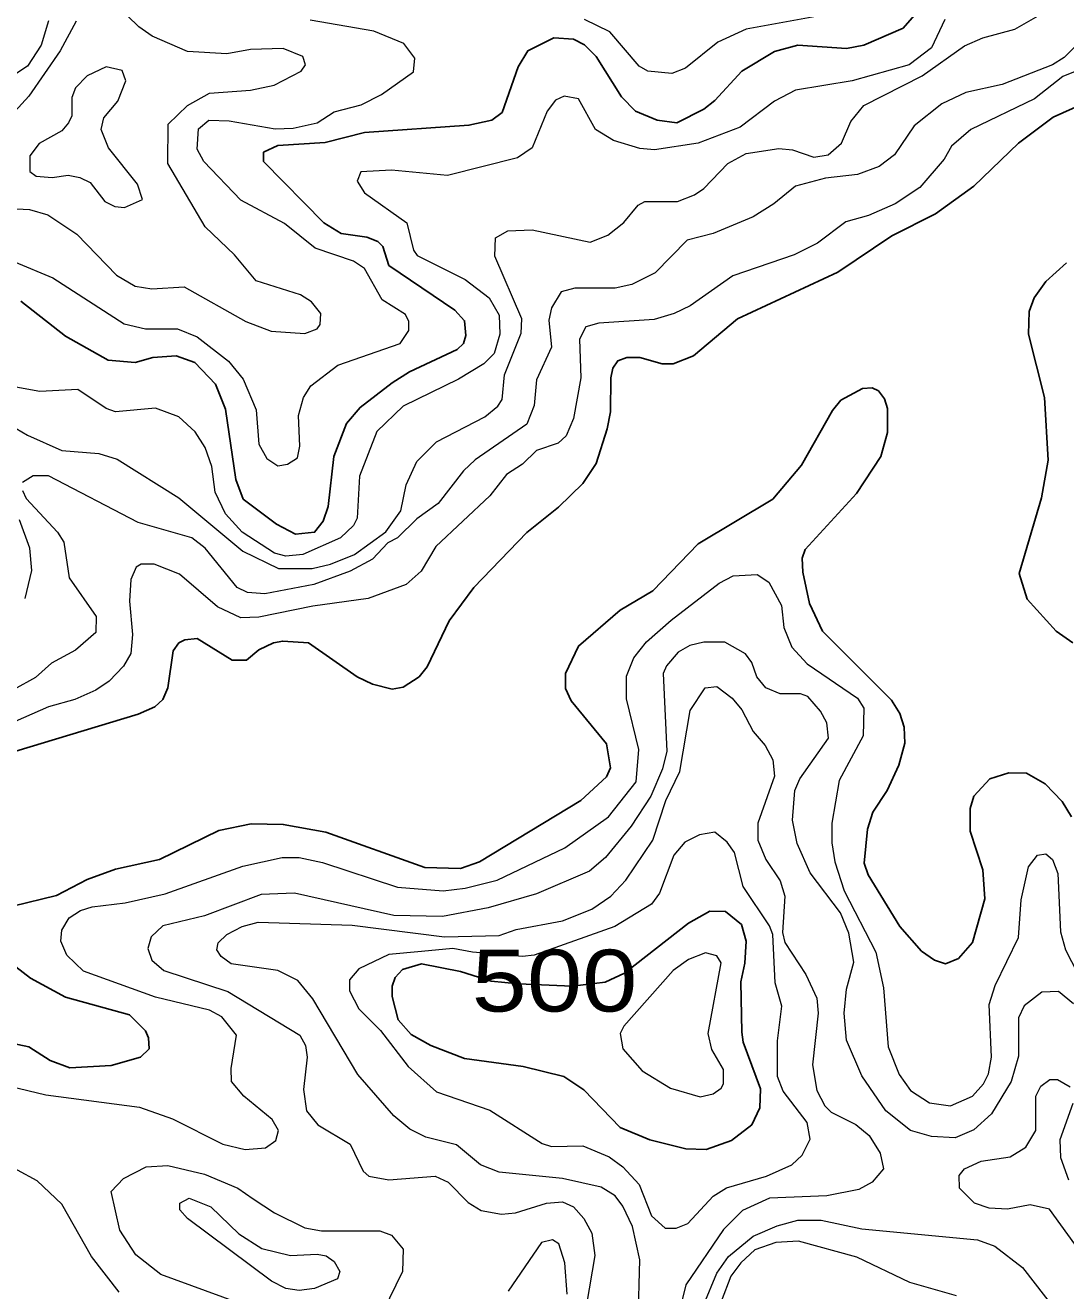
# Model space of a CAD drawing. Extents: x 577 to 602.9, y 7483.8 to 7511.6.
# Drawn here: x 599.479 to 600.825, y 7491.079 to 7492.716 of the extents above; entities that cross this region are included whole.
import ezdxf
from ezdxf.enums import TextEntityAlignment as Align

# ---------------------------------------------------------------- set-up
doc = ezdxf.new("R2010")
doc.units = 0
doc.header["$LTSCALE"] = 0.032
doc.layers.add('1', color=7, linetype='Continuous', lineweight=25)
doc.layers.add('2', color=7, linetype='Continuous', lineweight=13)
doc.layers.add('61', color=7, linetype='Continuous')

msp = doc.modelspace()

# ---------------------------------------------------------------- linework, layer by layer
at = {"layer": '1'}
for points in [[(600.6496, 7492.7525), (600.6146, 7492.712), (600.5637, 7492.6897), (600.5414, 7492.6857), (600.4786, 7492.6897), (600.4484, 7492.6818), (600.4063, 7492.6563), (600.3713, 7492.6182), (600.357, 7492.607), (600.322, 7492.5895), (600.2965, 7492.5927), (600.2687, 7492.6046), (600.2504, 7492.6229), (600.2178, 7492.6754), (600.2027, 7492.6905), (600.1884, 7492.6977), (600.1629, 7492.6993), (600.1295, 7492.6826), (600.1168, 7492.6619), (600.0961, 7492.603), (600.0826, 7492.5927), (600.0532, 7492.5863), (599.918, 7492.5768), (599.8671, 7492.5641), (599.8059, 7492.5601), (599.7876, 7492.5514), (599.7876, 7492.5394), (599.8655, 7492.4599), (599.8878, 7492.4464), (599.9212, 7492.4416), (599.9355, 7492.4361), (599.9419, 7492.4297), (599.9498, 7492.405), (600.0349, 7492.347), (600.0476, 7492.3335), (600.0492, 7492.3144), (600.046, 7492.3041), (600.0381, 7492.2961), (599.9761, 7492.2675), (599.9538, 7492.2532), (599.9125, 7492.2214), (599.895, 7492.2007), (599.8783, 7492.1577), (599.8711, 7492.0933), (599.8647, 7492.0743), (599.8536, 7492.0599), (599.829, 7492.0576), (599.8043, 7492.0703), (599.7614, 7492.1029), (599.7518, 7492.1283), (599.7383, 7492.219), (599.7256, 7492.2516), (599.6986, 7492.2794), (599.6747, 7492.2882), (599.6445, 7492.2858), (599.6214, 7492.2794), (599.5864, 7492.2826), (599.5316, 7492.3136), (599.4735, 7492.3589)], [(600.904, 7492.6396), (600.8086, 7492.5967), (600.7641, 7492.5633), (600.706, 7492.5076), (600.6567, 7492.4718), (600.6003, 7492.4432), (600.5303, 7492.3963), (600.4007, 7492.3359), (600.3434, 7492.2882), (600.3172, 7492.2778), (600.3029, 7492.2778), (600.2743, 7492.2858), (600.2576, 7492.2858), (600.2456, 7492.2818), (600.2393, 7492.2723), (600.2369, 7492.2595), (600.2361, 7492.2158), (600.2321, 7492.1935), (600.2178, 7492.149), (600.2003, 7492.1228), (600.1688, 7492.0923), (600.1279, 7492.0598), (600.0596, 7491.9884), (600.0278, 7491.9454), (599.9991, 7491.8858), (599.9888, 7491.8731), (599.9681, 7491.8596), (599.9538, 7491.8572), (599.9284, 7491.8635), (599.9085, 7491.8731), (599.8457, 7491.9168), (599.8123, 7491.9192), (599.8003, 7491.9168), (599.7813, 7491.9081), (599.7653, 7491.8945), (599.7471, 7491.8945), (599.7017, 7491.9224), (599.6858, 7491.9208), (599.6779, 7491.9168), (599.6707, 7491.9065), (599.6636, 7491.8588), (599.6572, 7491.8437), (599.6469, 7491.8341), (599.6254, 7491.8246), (599.4672, 7491.7769)], [(600.8341, 7491.9168), (600.8126, 7491.9319), (600.7752, 7491.9733), (600.7649, 7492.0067), (600.7935, 7492.1045), (600.8023, 7492.153), (600.7975, 7492.2341), (600.7768, 7492.316), (600.7776, 7492.3454), (600.784, 7492.3629), (600.7991, 7492.3844), (600.8261, 7492.4082)], [(599.4632, 7491.5765), (599.5196, 7491.59), (599.5594, 7491.6107), (599.596, 7491.6242), (599.6532, 7491.6369), (599.7296, 7491.6743), (599.7717, 7491.683), (599.8131, 7491.6822), (599.8679, 7491.6719), (599.996, 7491.6266), (600.0421, 7491.625), (600.0667, 7491.6337), (600.1979, 7491.7132), (600.2313, 7491.7435), (600.2361, 7491.7554), (600.2313, 7491.7864), (600.1852, 7491.8421), (600.178, 7491.858), (600.178, 7491.8771), (600.1947, 7491.9128), (600.2488, 7491.959), (600.291, 7491.9844), (600.3498, 7492.0448), (600.446, 7492.1029), (600.4834, 7492.1466), (600.5232, 7492.2174), (600.5343, 7492.2309), (600.5621, 7492.246), (600.5748, 7492.2468), (600.5828, 7492.2428), (600.5907, 7492.2325), (600.5947, 7492.2198), (600.5947, 7492.1888), (600.586, 7492.1577), (600.5542, 7492.11), (600.4882, 7492.0377), (600.4842, 7492.0265), (600.485, 7492.0083), (600.4937, 7491.9677), (600.5104, 7491.9319), (600.5995, 7491.8429), (600.6106, 7491.8254), (600.6162, 7491.8079), (600.617, 7491.7872), (600.609, 7491.7586), (600.5939, 7491.726), (600.5756, 7491.6981), (600.5685, 7491.6759), (600.5645, 7491.6321), (600.5693, 7491.617), (600.6106, 7491.5502), (600.6385, 7491.5184), (600.6552, 7491.5065), (600.6695, 7491.5017), (600.6862, 7491.5089), (600.7045, 7491.5296), (600.7204, 7491.586), (600.718, 7491.6234), (600.7013, 7491.6735), (600.7013, 7491.7029), (600.706, 7491.7188), (600.7267, 7491.7411), (600.7514, 7491.749)], [(600.7514, 7491.749), (600.7744, 7491.7482), (600.7983, 7491.7347), (600.8205, 7491.7117), (600.8325, 7491.6918)], [(599.4282, 7491.4063), (599.4839, 7491.3944), (599.5117, 7491.3769), (599.5371, 7491.3673), (599.5904, 7491.3705), (599.6286, 7491.3809), (599.6397, 7491.392), (599.6389, 7491.4063), (599.6349, 7491.4151), (599.6143, 7491.4357), (599.5316, 7491.4588), (599.4862, 7491.4834), (599.452, 7491.5097)]]:
    msp.add_lwpolyline(points, dxfattribs=at)
msp.add_lwpolyline([(600.0422, 7491.4917), (600.082, 7491.4793), (600.1172, 7491.4761), (600.1869, 7491.4728), (600.2293, 7491.478), (600.2544, 7491.4898), (600.3371, 7491.5542), (600.3649, 7491.5701), (600.3848, 7491.5693), (600.4055, 7491.5526), (600.4118, 7491.5311), (600.4102, 7491.5025), (600.4047, 7491.4787), (600.4063, 7491.4135), (600.4079, 7491.4007), (600.4301, 7491.3403), (600.4293, 7491.3157), (600.419, 7491.2934), (600.3927, 7491.2735), (600.3601, 7491.2616), (600.3339, 7491.2624), (600.287, 7491.2743), (600.2488, 7491.2902), (600.2019, 7491.3387), (600.1757, 7491.3562), (600.1232, 7491.3689), (600.0476, 7491.3793), (600.0039, 7491.396), (599.9785, 7491.4103), (599.9618, 7491.4294), (599.9538, 7491.4596), (599.9538, 7491.4731), (599.9578, 7491.4842), (599.9673, 7491.4946), (599.992, 7491.5017)], close=True, dxfattribs=at)
at = {"layer": '2'}
for points in [[(599.452, 7492.479), (599.4847, 7492.4774), (599.5085, 7492.4703), (599.5459, 7492.4456), (599.5976, 7492.3923), (599.6214, 7492.378), (599.6429, 7492.3748), (599.685, 7492.3772), (599.7646, 7492.3327), (599.7972, 7492.32), (599.8409, 7492.3168), (599.8568, 7492.3231), (599.8608, 7492.3287), (599.8616, 7492.343), (599.8496, 7492.3581), (599.8353, 7492.3669), (599.7781, 7492.3852), (599.7502, 7492.4186), (599.7121, 7492.4551), (599.6636, 7492.537), (599.6644, 7492.5879), (599.689, 7492.6118), (599.7176, 7492.6277), (599.7709, 7492.6317), (599.8011, 7492.638), (599.8361, 7492.6563), (599.8417, 7492.6643), (599.8385, 7492.6754), (599.8131, 7492.6857), (599.7709, 7492.6842), (599.7399, 7492.6786), (599.689, 7492.6818), (599.6437, 7492.7016), (599.6262, 7492.7136), (599.5968, 7492.7422)], [(599.5093, 7492.7215), (599.4998, 7492.6897), (599.4823, 7492.6627), (599.4322, 7492.6301)], [(599.5451, 7492.7207), (599.5244, 7492.6826), (599.4839, 7492.6237), (599.4338, 7492.5696)], [(599.4656, 7492.4098), (599.5149, 7492.3891), (599.6071, 7492.3295), (599.6349, 7492.3231), (599.6763, 7492.3231), (599.7017, 7492.3128), (599.7423, 7492.281), (599.7614, 7492.2579), (599.7781, 7492.2182), (599.7813, 7492.1737), (599.7916, 7492.1554), (599.8059, 7492.1458), (599.8186, 7492.1482), (599.8313, 7492.1562), (599.8345, 7492.1713), (599.8329, 7492.211), (599.8393, 7492.2341), (599.8488, 7492.2492), (599.8838, 7492.2762), (599.9641, 7492.3041), (599.9753, 7492.3208), (599.9753, 7492.3327), (599.9713, 7492.3414), (599.9411, 7492.3605), (599.918, 7492.4011), (599.9037, 7492.4106), (599.8544, 7492.4273), (599.8147, 7492.4591), (599.7582, 7492.4893), (599.7105, 7492.5394), (599.7017, 7492.5553), (599.7033, 7492.5816), (599.7168, 7492.5927), (599.7431, 7492.5919), (599.8027, 7492.5816), (599.8258, 7492.5824), (599.8568, 7492.5895), (599.8791, 7492.6038), (599.914, 7492.6126), (599.9403, 7492.6261), (599.9816, 7492.6555), (599.9832, 7492.673), (599.9689, 7492.6921), (599.93, 7492.708), (599.848, 7492.7223)], [(600.6687, 7492.7231), (600.6512, 7492.6865), (600.6225, 7492.6643), (600.5486, 7492.6436), (600.4754, 7492.6317), (600.4484, 7492.6174), (600.4039, 7492.584), (600.3498, 7492.5633), (600.2933, 7492.5545), (600.2743, 7492.5561), (600.2401, 7492.5665), (600.217, 7492.5808), (600.1947, 7492.6205), (600.1765, 7492.6237), (600.1653, 7492.6189), (600.1542, 7492.6046), (600.1351, 7492.5569), (600.116, 7492.5442), (600.0254, 7492.5211), (599.953, 7492.5283), (599.9133, 7492.5259), (599.9085, 7492.514), (599.918, 7492.4989), (599.9729, 7492.4599), (599.9816, 7492.4249), (599.9864, 7492.4178), (600.0484, 7492.3868), (600.0794, 7492.3629), (600.0922, 7492.3406), (600.093, 7492.316), (600.0858, 7492.2913), (600.0723, 7492.2778), (600.0397, 7492.2579), (599.9681, 7492.223), (599.9339, 7492.1904), (599.9117, 7492.1323), (599.9085, 7492.0782), (599.9037, 7492.0687), (599.887, 7492.0528), (599.8385, 7492.0313), (599.8162, 7492.0289), (599.8019, 7492.0329), (599.7598, 7492.0599), (599.7383, 7492.0838), (599.7248, 7492.1116), (599.7208, 7492.145), (599.7121, 7492.1697), (599.6993, 7492.1896), (599.6779, 7492.2094), (599.6477, 7492.2206), (599.596, 7492.2158), (599.584, 7492.2198), (599.5475, 7492.2444), (599.4982, 7492.242), (599.4672, 7492.2476)], [(599.5268, 7492.1657), (599.5745, 7492.1617), (599.5984, 7492.1546), (599.6779, 7492.1045), (599.7606, 7492.0353), (599.8067, 7492.013), (599.8504, 7492.013), (599.8743, 7492.0186), (599.9053, 7492.0313), (599.9459, 7492.0607), (599.9649, 7492.0878), (599.9721, 7492.1212), (599.9856, 7492.1514), (600.0111, 7492.1768), (600.0739, 7492.2094), (600.0906, 7492.223), (600.0961, 7492.2317), (600.0993, 7492.2635), (600.1208, 7492.3176), (600.1216, 7492.3359), (600.0866, 7492.417), (600.0874, 7492.4408), (600.1033, 7492.4496), (600.1351, 7492.4512), (600.2099, 7492.4353), (600.2329, 7492.444), (600.2536, 7492.4607), (600.2719, 7492.483), (600.2806, 7492.4877), (600.3228, 7492.4877), (600.345, 7492.4965), (600.357, 7492.5044), (600.388, 7492.537), (600.4118, 7492.5498), (600.454, 7492.5561), (600.4715, 7492.5545), (600.4993, 7492.545), (600.5176, 7492.5482), (600.5351, 7492.5633), (600.547, 7492.5911), (600.5637, 7492.6118), (600.6392, 7492.65), (600.6941, 7492.6889), (600.718, 7492.6993), (600.7593, 7492.7104), (600.7895, 7492.7279)], [(600.5065, 7492.7279), (600.4118, 7492.7104), (600.3752, 7492.6937), (600.3331, 7492.6603), (600.3156, 7492.6531), (600.2846, 7492.6563), (600.2735, 7492.6627), (600.2353, 7492.7072), (600.2027, 7492.7231)], [(600.8444, 7492.6953), (600.8229, 7492.6738), (600.8078, 7492.6643), (600.7426, 7492.6388), (600.6957, 7492.6285), (600.6647, 7492.6142), (600.6289, 7492.5856), (600.6035, 7492.5482), (600.5836, 7492.5331), (600.5558, 7492.5227), (600.5144, 7492.518), (600.4754, 7492.5076), (600.4476, 7492.4846), (600.4206, 7492.4679), (600.3689, 7492.4464)], [(600.8738, 7492.6706), (600.8213, 7492.6492), (600.7848, 7492.6205), (600.7021, 7492.5808), (600.6774, 7492.5593), (600.6679, 7492.5426), (600.6361, 7492.506), (600.6043, 7492.4846), (600.5701, 7492.4695), (600.5406, 7492.4615), (600.5041, 7492.4337), (600.4739, 7492.4186), (600.3943, 7492.3915), (600.3395, 7492.3526), (600.3188, 7492.343), (600.2926, 7492.3351), (600.221, 7492.3303), (600.2043, 7492.3255), (600.1963, 7492.3096), (600.1979, 7492.2595), (600.1884, 7492.207), (600.1788, 7492.1848), (600.1685, 7492.1752), (600.1407, 7492.1657), (600.1224, 7492.1482), (600.1017, 7492.1347), (600.0802, 7492.1069), (600.0103, 7492.0417), (599.9912, 7492.0098), (599.9721, 7491.9924), (599.9228, 7491.9741), (599.8512, 7491.9645), (599.7813, 7491.9502), (599.7582, 7491.9494), (599.728, 7491.9637), (599.6787, 7492.0059), (599.6461, 7492.0186), (599.6294, 7492.0186), (599.623, 7492.0146), (599.6159, 7491.9987)], [(600.3689, 7492.4464), (600.3355, 7492.4376), (600.2941, 7492.3955), (600.2639, 7492.3804), (600.2425, 7492.3756), (600.19, 7492.3756), (600.1725, 7492.3709), (600.1598, 7492.3502), (600.1566, 7492.3343), (600.1598, 7492.2993), (600.1407, 7492.2571), (600.1375, 7492.2237), (600.1279, 7492.1999), (600.0612, 7492.1538), (600.046, 7492.1395), (600.0134, 7492.0973), (599.9856, 7492.0774), (599.961, 7492.0528), (599.9482, 7492.0464), (599.9284, 7492.025), (599.8997, 7492.0098), (599.8528, 7491.9924), (599.7892, 7491.9804), (599.7669, 7491.982), (599.7534, 7491.9884), (599.7121, 7492.0393), (599.6946, 7492.0528), (599.6254, 7492.0727), (599.5093, 7492.1331), (599.4894, 7492.1331), (599.4759, 7492.1244)], [(599.4306, 7492.2158), (599.4823, 7492.1856), (599.5268, 7492.1657)], [(599.4759, 7492.114), (599.4807, 7492.1037), (599.5212, 7492.0599), (599.5292, 7492.0472), (599.5363, 7492.0011), (599.5713, 7491.951), (599.5705, 7491.9303), (599.5443, 7491.9073), (599.5133, 7491.8906), (599.4926, 7491.8723), (599.4648, 7491.8564)], [(599.4791, 7491.9741), (599.4878, 7492.0106), (599.4854, 7492.0393), (599.4719, 7492.0758)], [(599.4465, 7491.3467), (599.5061, 7491.3324), (599.627, 7491.3165), (599.6699, 7491.3013), (599.7351, 7491.2687), (599.7638, 7491.2616), (599.79, 7491.264), (599.8035, 7491.2735), (599.8067, 7491.2862), (599.7987, 7491.3005), (599.7622, 7491.3308), (599.7463, 7491.3498), (599.7455, 7491.3665), (599.7526, 7491.4095), (599.7335, 7491.4333), (599.7176, 7491.4421), (599.6477, 7491.4588), (599.5546, 7491.4922), (599.5332, 7491.5129), (599.5252, 7491.5311), (599.5268, 7491.5455), (599.5363, 7491.5614), (599.5507, 7491.5709), (599.5658, 7491.5757), (599.6087, 7491.5805), (599.6604, 7491.5924), (599.7606, 7491.6282), (599.8115, 7491.6393), (599.8337, 7491.6393), (599.864, 7491.6329), (599.961, 7491.6011), (600.0198, 7491.5964), (600.0484, 7491.5995), (600.0898, 7491.6099), (600.1773, 7491.652), (600.2337, 7491.6918), (600.2695, 7491.7371), (600.2727, 7491.7792), (600.2568, 7491.8444), (600.2568, 7491.8739), (600.2663, 7491.8977), (600.283, 7491.9184), (600.3148, 7491.9462), (600.3768, 7491.9939), (600.3951, 7492.0035), (600.4261, 7492.0051), (600.4412, 7491.9955), (600.4572, 7491.9653), (600.4603, 7491.9367), (600.4707, 7491.9112), (600.4905, 7491.8898), (600.5558, 7491.8452), (600.5637, 7491.8325), (600.5629, 7491.7967), (600.5319, 7491.7387), (600.5224, 7491.6838), (600.5224, 7491.6584), (600.5263, 7491.6337), (600.5383, 7491.5964), (600.5796, 7491.5168), (600.5892, 7491.4707), (600.5955, 7491.3944), (600.6098, 7491.3586), (600.6241, 7491.3379), (600.6488, 7491.322), (600.6758, 7491.318), (600.7045, 7491.3308), (600.7188, 7491.3467), (600.7251, 7491.3594), (600.7291, 7491.3809), (600.7259, 7491.4492), (600.7339, 7491.4739), (600.7641, 7491.5359), (600.7673, 7491.5844), (600.7768, 7491.6274)], [(599.6159, 7491.9987), (599.6143, 7491.9709), (599.6182, 7491.9279), (599.6159, 7491.9033), (599.6063, 7491.8866), (599.588, 7491.8675), (599.5705, 7491.8556), (599.5435, 7491.8437), (599.5093, 7491.8341), (599.4664, 7491.815)], [(600.8349, 7491.45), (600.8158, 7491.4659), (600.7943, 7491.4651), (600.7712, 7491.4477), (600.7641, 7491.4318), (600.7641, 7491.3825), (600.7545, 7491.3498), (600.7291, 7491.3077), (600.706, 7491.287), (600.6822, 7491.2767), (600.6512, 7491.2783), (600.6241, 7491.2862), (600.5923, 7491.3117), (600.5613, 7491.357), (600.5414, 7491.4031), (600.5383, 7491.4381), (600.5414, 7491.4691), (600.551, 7491.5041), (600.5446, 7491.5415), (600.5335, 7491.5677), (600.4945, 7491.6194), (600.4778, 7491.6576), (600.4715, 7491.6878), (600.4746, 7491.726), (600.481, 7491.7411), (600.5184, 7491.7936), (600.516, 7491.8134), (600.508, 7491.8285), (600.4913, 7491.8476), (600.4818, 7491.8508), (600.4556, 7491.8508), (600.4373, 7491.8588), (600.4253, 7491.8731), (600.419, 7491.8914), (600.411, 7491.9025), (600.384, 7491.9176), (600.357, 7491.9176), (600.3387, 7491.9136), (600.3236, 7491.9049), (600.3085, 7491.8874), (600.3045, 7491.8771)], [(600.3045, 7491.8771), (600.3092, 7491.7769), (600.3037, 7491.7538), (600.2886, 7491.7188), (600.2631, 7491.6798), (600.2297, 7491.6393), (600.2091, 7491.6218), (600.1407, 7491.5924), (600.0779, 7491.5741), (600.019, 7491.563), (599.9562, 7491.5645), (599.8274, 7491.5932), (599.7844, 7491.5916), (599.7113, 7491.5638), (599.6572, 7491.551), (599.6421, 7491.5367), (599.6381, 7491.5216), (599.6429, 7491.5065), (599.6588, 7491.493), (599.7415, 7491.4659), (599.8345, 7491.4095), (599.8417, 7491.396), (599.8441, 7491.3809), (599.8393, 7491.3395), (599.8433, 7491.3117), (599.8576, 7491.2934), (599.8997, 7491.2687), (599.9164, 7491.2338), (599.9236, 7491.2274), (599.9498, 7491.2226), (600.0095, 7491.2274), (600.0262, 7491.2194), (600.0524, 7491.1932), (600.0691, 7491.1829), (600.0953, 7491.1781), (600.1136, 7491.1797), (600.1534, 7491.1924), (600.1741, 7491.194), (600.1884, 7491.1876), (600.2019, 7491.1725), (600.2122, 7491.1534), (600.2162, 7491.1248), (600.2051, 7491.0612)], [(600.0214, 7491.5367), (600.0922, 7491.5383), (600.1144, 7491.5463), (600.1741, 7491.5574), (600.2122, 7491.5725), (600.2369, 7491.5892), (600.256, 7491.6099), (600.291, 7491.6616), (600.3077, 7491.7132), (600.3259, 7491.7506), (600.3395, 7491.8293), (600.3586, 7491.8588), (600.3737, 7491.8604), (600.3935, 7491.8452), (600.4063, 7491.8301), (600.4206, 7491.8023), (600.4365, 7491.784), (600.446, 7491.7657), (600.4484, 7491.7443), (600.4269, 7491.6838), (600.4269, 7491.6616), (600.4373, 7491.6369), (600.4556, 7491.6091), (600.4619, 7491.5892), (600.4587, 7491.5423), (600.4619, 7491.5296), (600.489, 7491.4882), (600.5033, 7491.4572), (600.5049, 7491.4381), (600.4977, 7491.3713), (600.5033, 7491.3379), (600.5136, 7491.318), (600.5216, 7491.3101), (600.5534, 7491.2942), (600.5709, 7491.2799), (600.5852, 7491.2568), (600.5892, 7491.2369), (600.5748, 7491.2194), (600.5573, 7491.2099), (600.516, 7491.2019), (600.442, 7491.1988), (600.4071, 7491.1829), (600.3824, 7491.1582), (600.3339, 7491.0866), (600.3252, 7491.0517)], [(600.7768, 7491.6274), (600.7887, 7491.6425), (600.7991, 7491.6441), (600.8078, 7491.6369), (600.815, 7491.6186), (600.8182, 7491.5431), (600.8245, 7491.52), (600.8404, 7491.4898)], [(599.7399, 7491.5399), (599.7598, 7491.5502), (599.7805, 7491.5558), (599.9021, 7491.5518), (600.0214, 7491.5367)], [(600.2719, 7491.0389), (600.2743, 7491.1192), (600.2647, 7491.1622), (600.252, 7491.1884), (600.2425, 7491.2019), (600.2242, 7491.2131), (600.1741, 7491.2242), (600.0922, 7491.2322), (600.0683, 7491.2417), (600.0373, 7491.2679), (599.9975, 7491.2775), (599.9769, 7491.2878), (599.9562, 7491.3053), (599.9093, 7491.3586), (599.8512, 7491.4564), (599.8321, 7491.4803), (599.8059, 7491.493), (599.7455, 7491.5017), (599.7327, 7491.5113), (599.7272, 7491.52), (599.7288, 7491.5288), (599.7399, 7491.5399)], [(600.8659, 7491.0986), (600.8038, 7491.1845), (600.7792, 7491.19), (600.7498, 7491.1845), (600.7259, 7491.186), (600.7068, 7491.1924), (600.6878, 7491.2115), (600.687, 7491.2282), (600.6941, 7491.2369), (600.7156, 7491.2465), (600.753, 7491.252), (600.7736, 7491.2648), (600.7864, 7491.2862), (600.7864, 7491.3308), (600.7927, 7491.3435), (600.8046, 7491.3522), (600.8142, 7491.3522), (600.8309, 7491.3427)], [(600.8341, 7491.3212), (600.8174, 7491.2743), (600.8182, 7491.2512), (600.8285, 7491.2226)], [(599.6007, 7491.0771), (599.565, 7491.1232), (599.5268, 7491.1908), (599.495, 7491.221), (599.4433, 7491.2489)], [(600.357, 7491.0612), (600.3737, 7491.1018), (600.3888, 7491.1232), (600.4206, 7491.1495), (600.4516, 7491.163), (600.4786, 7491.1701), (600.5088, 7491.1701), (600.5613, 7491.159), (600.7108, 7491.1447), (600.7331, 7491.1367), (600.7689, 7491.1089), (600.8388, 7491.0191)], [(600.1804, 7491.0747), (600.1773, 7491.1153), (600.1693, 7491.1399), (600.1613, 7491.1447), (600.147, 7491.1415)], [(600.147, 7491.1415), (600.1041, 7491.0787)], [(600.6838, 7491.0723), (600.6233, 7491.0898), (600.555, 7491.1224), (600.4794, 7491.1431), (600.45, 7491.1415), (600.423, 7491.132), (600.4047, 7491.1153), (600.3919, 7491.0978), (600.3792, 7491.0652)]]:
    msp.add_lwpolyline(points, dxfattribs=at)
for points in [[(599.5499, 7492.5188), (599.5634, 7492.5124), (599.5825, 7492.4877), (599.5952, 7492.4814), (599.6079, 7492.4798), (599.631, 7492.4901), (599.6246, 7492.51), (599.5872, 7492.5569), (599.5777, 7492.5808), (599.5809, 7492.5959), (599.5992, 7492.6174), (599.6095, 7492.6436), (599.6047, 7492.6571), (599.584, 7492.6619), (599.5594, 7492.65), (599.5443, 7492.6349), (599.5395, 7492.6221), (599.5395, 7492.5983), (599.5355, 7492.5895), (599.5268, 7492.5792), (599.4974, 7492.5625), (599.4854, 7492.5466), (599.4854, 7492.5267), (599.4934, 7492.5203), (599.5141, 7492.5188), (599.5347, 7492.5219)], [(599.992, 7491.5176), (599.9498, 7491.5137), (599.9109, 7491.4954), (599.8989, 7491.4811), (599.8989, 7491.4667), (599.9109, 7491.4437), (599.9387, 7491.4158), (599.9745, 7491.3689), (600.0111, 7491.3363), (600.0802, 7491.3125), (600.1478, 7491.2695), (600.1598, 7491.2656), (600.2003, 7491.2664), (600.2345, 7491.252), (600.252, 7491.2393), (600.2735, 7491.2163), (600.2894, 7491.1757), (600.3069, 7491.1598), (600.3212, 7491.1598), (600.3363, 7491.1662), (600.3689, 7491.2012), (600.3864, 7491.2123), (600.4381, 7491.2274), (600.4707, 7491.2417), (600.4842, 7491.2544), (600.4945, 7491.2751), (600.4905, 7491.2966), (600.4595, 7491.3371), (600.4524, 7491.3562), (600.4524, 7491.4023), (600.4579, 7491.4469), (600.4492, 7491.4771), (600.446, 7491.5399), (600.442, 7491.551), (600.4079, 7491.6019), (600.3967, 7491.6457), (600.3872, 7491.6592), (600.3713, 7491.6719), (600.3514, 7491.6687), (600.3323, 7491.6592), (600.318, 7491.6425), (600.2997, 7491.5932), (600.2894, 7491.5789), (600.2417, 7491.5502), (600.1375, 7491.5129), (600.1225, 7491.5115), (600.058, 7491.5168), (600.0325, 7491.5216)], [(600.252, 7491.392), (600.2774, 7491.3634), (600.314, 7491.3411), (600.3522, 7491.33), (600.3689, 7491.3339), (600.3792, 7491.3411), (600.3824, 7491.3467), (600.3824, 7491.365), (600.3673, 7491.3912), (600.3625, 7491.4119), (600.3792, 7491.5033), (600.3737, 7491.5121), (600.3593, 7491.516), (600.3371, 7491.5073), (600.3172, 7491.493), (600.2536, 7491.4214), (600.2488, 7491.4119)], [(599.7741, 7491.198), (599.8019, 7491.1797), (599.8409, 7491.1606), (599.8624, 7491.1566), (599.9379, 7491.1566), (599.953, 7491.1511), (599.9681, 7491.1328), (599.9673, 7491.1041), (599.9419, 7491.0517), (599.9323, 7491.0421), (599.9053, 7491.0278), (599.8608, 7491.0143), (599.8361, 7491.0183), (599.8019, 7491.0405), (599.7526, 7491.0644), (599.6548, 7491.1002), (599.6222, 7491.1256), (599.6015, 7491.1574), (599.5904, 7491.2075), (599.6063, 7491.2242), (599.6357, 7491.2393), (599.6636, 7491.2409), (599.7113, 7491.2298), (599.7542, 7491.2115)], [(599.6914, 7491.1988), (599.7192, 7491.1876), (599.7558, 7491.1526), (599.7852, 7491.1336), (599.8226, 7491.1248), (599.8568, 7491.1264), (599.8687, 7491.124), (599.8791, 7491.1169), (599.8862, 7491.1041), (599.883, 7491.0946), (599.8536, 7491.0819), (599.8337, 7491.0795), (599.8162, 7491.0819), (599.798, 7491.0914), (599.689, 7491.1725), (599.6795, 7491.1837), (599.6795, 7491.1924)]]:
    msp.add_lwpolyline(points, close=True, dxfattribs=at)

# ---------------------------------------------------------------- texts
at = {"layer": '61', "width": 1.2}
msp.add_text('500', height=0.08, dxfattribs=at).set_placement((600.1639, 7491.4401), align=Align.CENTER)

doc.saveas('drawing.dxf')
